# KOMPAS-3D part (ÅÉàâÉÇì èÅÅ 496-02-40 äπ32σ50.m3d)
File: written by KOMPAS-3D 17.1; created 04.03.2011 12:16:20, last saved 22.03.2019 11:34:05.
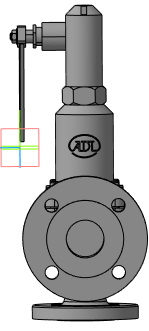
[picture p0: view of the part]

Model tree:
1. Плоскость XY
2. Плоскость ZX
3. Плоскость ZY
4. Ось X
5. Ось Y
6. Ось Z
7. Начало координат
8. Операция без истории:2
